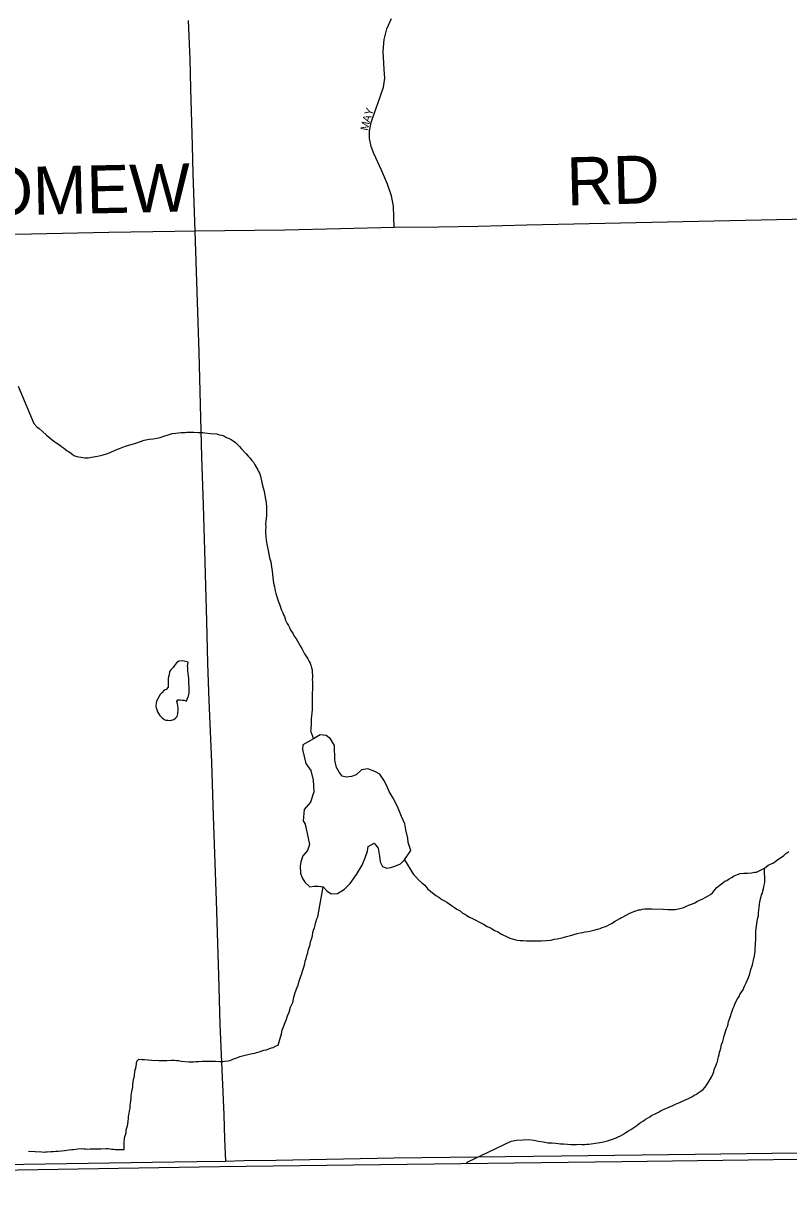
# Model space of a CAD drawing. Extents: x -10.1 to 68, y -9.5 to 29.2.
# Drawn here: x 3.456 to 4.36, y 16.795 to 18.175 of the extents above; entities that cross this region are included whole.
import ezdxf

# ---------------------------------------------------------------- set-up
doc = ezdxf.new("R2010")
doc.units = 0
for name, color, linetype in [('GM_X_Adjacent_County', 7, 'Continuous'), ('GM_X_County_Road', 7, 'Continuous'), ('GM_X_Minor_Lake', 7, 'Continuous'), ('GM_X_Minor_River', 7, 'Continuous'), ('GM_X_Township_Road', 7, 'Continuous'), ('GM_X_Township_Road_Text', 7, 'Continuous'), ('GM_X_Township_Subdivision', 7, 'Continuous'), ('GM_X_Township_Subdivision_Text', 7, 'Continuous')]:
    doc.layers.add(name, color=color, linetype=linetype)

msp = doc.modelspace()

# ---------------------------------------------------------------- linework, layer by layer
at = {"layer": 'GM_X_Adjacent_County'}
msp.add_lwpolyline([(8.9, 16.8967), (8.5023, 16.8904), (7.9665, 16.8821), (7.5233, 16.8774), (6.5083, 16.8667), (6.2435, 16.8638), (4.8206, 16.8372), (4.1632, 16.8285), (3.6875, 16.8223), (2.8045, 16.808), (2.1, 16.7954)], dxfattribs=at)
at = {"layer": 'GM_X_County_Road'}
msp.add_lwpolyline([(3.6506, 18.1785), (3.6523, 18.1327), (3.6533, 18.0978), (3.6553, 18.0303), (3.656, 17.9971), (3.6584, 17.9291), (3.6632, 17.7858), (3.6664, 17.6621), (3.6683, 17.6049), (3.6698, 17.5516), (3.6722, 17.4679), (3.6734, 17.4177), (3.6751, 17.374), (3.6782, 17.3012), (3.6802, 17.2377), (3.6838, 17.1371), (3.6864, 17.049), (3.6881, 16.9909), (3.6925, 16.8838), (3.6934, 16.8551), (3.6947, 16.8292)], dxfattribs=at)
at = {"layer": 'GM_X_Minor_Lake'}
for points in [[(3.6174, 17.3813), (3.613, 17.3731), (3.6126, 17.3708), (3.6123, 17.3678), (3.6128, 17.3655), (3.6136, 17.3633), (3.6144, 17.3606), (3.6156, 17.3587), (3.6172, 17.3561), (3.6195, 17.3539), (3.6222, 17.3517), (3.6241, 17.3509), (3.6264, 17.3506), (3.6283, 17.3503), (3.631, 17.3507), (3.6336, 17.3515), (3.6355, 17.3531), (3.6374, 17.355), (3.6384, 17.3581), (3.6384, 17.36), (3.6387, 17.3623), (3.6387, 17.3642), (3.6382, 17.368), (3.6378, 17.3699), (3.6373, 17.3729), (3.6384, 17.3749), (3.6415, 17.3749), (3.6434, 17.3746), (3.6457, 17.3743), (3.6484, 17.3732), (3.6495, 17.3755), (3.6502, 17.3774), (3.6509, 17.3793), (3.6512, 17.3812), (3.6516, 17.3835), (3.6519, 17.3858), (3.6518, 17.3904), (3.6513, 17.3942), (3.6512, 17.3968), (3.6512, 17.3991), (3.6512, 17.401), (3.6511, 17.4029), (3.6506, 17.4063), (3.6502, 17.409), (3.6502, 17.4113), (3.6501, 17.4132), (3.6497, 17.4143), (3.6507, 17.4193)], [(3.6507, 17.4193), (3.6442, 17.421), (3.6393, 17.4205), (3.6367, 17.4186), (3.6345, 17.4155), (3.6326, 17.4132), (3.63, 17.4104), (3.6285, 17.4085), (3.6279, 17.4043), (3.6272, 17.402), (3.6268, 17.4001), (3.6269, 17.3948), (3.627, 17.3925), (3.6267, 17.3898), (3.6245, 17.3871), (3.6222, 17.3863), (3.6192, 17.3832), (3.6174, 17.3813)], [(3.9063, 17.1855), (3.9137, 17.1966), (3.9106, 17.2061), (3.9101, 17.2114), (3.9077, 17.2212), (3.9065, 17.228), (3.9026, 17.2367), (3.898, 17.2488), (3.8929, 17.2586), (3.8883, 17.2666), (3.8855, 17.273), (3.8817, 17.2798), (3.877, 17.287), (3.8713, 17.2899), (3.863, 17.2932), (3.8554, 17.292), (3.849, 17.2862), (3.8437, 17.2842), (3.8373, 17.2834), (3.8324, 17.2845), (3.8289, 17.2894), (3.8258, 17.2947), (3.8238, 17.3034), (3.8236, 17.3209), (3.8186, 17.3288), (3.8136, 17.3325), (3.8064, 17.3336), (3.7985, 17.3285), (3.7861, 17.3215)], [(3.7861, 17.3215), (3.7858, 17.3162), (3.7898, 17.2995), (3.7955, 17.2912), (3.7983, 17.2799), (3.7992, 17.2662), (3.7952, 17.2536), (3.7878, 17.2451), (3.7864, 17.2318), (3.7888, 17.2277)], [(3.7888, 17.2277), (3.7939, 17.2038), (3.7917, 17.1966), (3.7861, 17.1904), (3.7836, 17.1832), (3.7829, 17.1782), (3.7833, 17.1698), (3.7853, 17.1642), (3.7884, 17.1593), (3.7945, 17.1536), (3.7994, 17.1545), (3.8047, 17.1545), (3.81, 17.1538), (3.8146, 17.149), (3.8196, 17.1452), (3.8272, 17.1457), (3.8355, 17.1507), (3.8422, 17.1577), (3.8496, 17.1684), (3.8563, 17.1791), (3.86, 17.1891), (3.8626, 17.1959), (3.8633, 17.2013), (3.8704, 17.2052), (3.875, 17.1995), (3.8767, 17.19), (3.8775, 17.1832), (3.8802, 17.1775), (3.8852, 17.1757), (3.8901, 17.1765), (3.895, 17.1781), (3.9014, 17.1808), (3.9063, 17.1855)]]:
    msp.add_lwpolyline(points, dxfattribs=at)
at = {"layer": 'GM_X_Minor_River'}
for points in [[(3.4494, 17.746), (3.4681, 17.7016), (3.4716, 17.6979), (3.4743, 17.6957), (3.4778, 17.6927), (3.4829, 17.6879), (3.4875, 17.6842), (3.4918, 17.6809), (3.4953, 17.6783), (3.4984, 17.6765), (3.5007, 17.6746), (3.503, 17.6728), (3.5053, 17.6713), (3.5076, 17.6694), (3.51, 17.668), (3.5127, 17.6661), (3.5154, 17.6639), (3.5188, 17.6628), (3.5284, 17.6612), (3.5322, 17.6612), (3.5364, 17.6617), (3.5409, 17.6626), (3.5455, 17.6635), (3.55, 17.6647), (3.5541, 17.6659), (3.5583, 17.6675), (3.5643, 17.67), (3.5692, 17.672), (3.5753, 17.6744), (3.5817, 17.6765), (3.5874, 17.6781), (3.593, 17.6801), (3.5987, 17.6818), (3.6044, 17.6831), (3.6093, 17.6835), (3.6135, 17.6844), (3.6176, 17.6853), (3.6218, 17.6865), (3.6267, 17.6881), (3.6316, 17.6898), (3.6358, 17.6902), (3.6392, 17.6907), (3.6422, 17.6911), (3.6449, 17.6912), (3.6468, 17.6912), (3.6487, 17.6913), (3.6514, 17.6914), (3.654, 17.6914), (3.6574, 17.6915), (3.6624, 17.6912), (3.6677, 17.691), (3.6704, 17.6906), (3.6769, 17.69), (3.6845, 17.6894), (3.6872, 17.6884), (3.6902, 17.6877), (3.6933, 17.6866), (3.696, 17.6851), (3.6991, 17.6841), (3.7014, 17.6826), (3.7037, 17.6811), (3.7064, 17.6793), (3.7088, 17.6767), (3.7111, 17.6744), (3.7131, 17.6722), (3.7189, 17.6659), (3.7216, 17.6629), (3.724, 17.6607), (3.7255, 17.6584), (3.7279, 17.6558), (3.7295, 17.6528), (3.7307, 17.6509), (3.7318, 17.649), (3.7327, 17.6468), (3.7338, 17.6449), (3.735, 17.643), (3.7355, 17.6408), (3.7363, 17.6373), (3.7371, 17.6339), (3.738, 17.6298), (3.7392, 17.6256), (3.7405, 17.6215), (3.7413, 17.6165), (3.7418, 17.612), (3.7427, 17.6082), (3.7432, 17.6025), (3.7433, 17.5979), (3.743, 17.593), (3.7427, 17.5892), (3.7424, 17.5857), (3.7421, 17.5827), (3.7422, 17.5793), (3.7419, 17.5755), (3.742, 17.572), (3.7425, 17.5679), (3.7429, 17.5633)], [(3.7429, 17.5633), (3.7439, 17.5569), (3.7451, 17.5516), (3.746, 17.547), (3.7468, 17.5428), (3.7481, 17.5379), (3.749, 17.5322), (3.7499, 17.5269), (3.7508, 17.5197), (3.7513, 17.5129), (3.7526, 17.5083), (3.753, 17.5061), (3.7534, 17.5038), (3.7543, 17.5004), (3.7572, 17.4909), (3.7584, 17.4879), (3.7596, 17.4845), (3.7608, 17.4808), (3.7624, 17.4777), (3.7632, 17.4755), (3.7644, 17.4732), (3.7656, 17.4691), (3.7676, 17.4653), (3.7692, 17.4627), (3.7704, 17.4604), (3.7716, 17.4574), (3.7732, 17.4552), (3.7748, 17.4529), (3.776, 17.4503), (3.7783, 17.4469), (3.7795, 17.445), (3.7811, 17.4424), (3.7831, 17.4386), (3.7847, 17.4356), (3.7863, 17.4322), (3.7882, 17.4292), (3.7898, 17.427), (3.7918, 17.4232), (3.7934, 17.4202), (3.7946, 17.418), (3.7954, 17.4157), (3.7962, 17.4127), (3.797, 17.4104), (3.7971, 17.407), (3.7976, 17.4036), (3.7976, 17.4009), (3.7973, 17.399), (3.7974, 17.3956), (3.7975, 17.3922), (3.7976, 17.388), (3.7973, 17.3823), (3.797, 17.3777), (3.7971, 17.3739), (3.7972, 17.3712), (3.7972, 17.3686), (3.7973, 17.3659), (3.797, 17.3629), (3.7967, 17.3594), (3.7964, 17.3556), (3.7961, 17.3526), (3.7959, 17.3453), (3.7956, 17.3419), (3.7956, 17.3392), (3.7953, 17.3381), (3.7985, 17.3285)], [(4.2681, 17.1445), (4.2707, 17.1468), (4.2729, 17.1496), (4.2755, 17.153), (4.2793, 17.1562), (4.2826, 17.1585), (4.2849, 17.1605), (4.2871, 17.1613), (4.2901, 17.1633), (4.2928, 17.1648), (4.2961, 17.1668), (4.2999, 17.1684), (4.3029, 17.1693), (4.3075, 17.1697), (4.312, 17.1698), (4.3166, 17.1703), (4.3204, 17.1708), (4.3223, 17.1708), (4.3272, 17.1732), (4.3317, 17.1756), (4.3362, 17.1792), (4.3418, 17.1816), (4.3441, 17.1831), (4.346, 17.1847), (4.3546, 17.1906), (4.3572, 17.1929), (4.3605, 17.1953)], [(3.9063, 17.1855), (3.9167, 17.1681), (3.9195, 17.1655), (3.923, 17.1621), (3.9265, 17.1588), (3.9304, 17.1555), (3.9339, 17.151), (3.9389, 17.1469), (3.9432, 17.1432), (3.9467, 17.1414), (3.949, 17.1399), (3.9513, 17.1384), (3.9536, 17.137), (3.9563, 17.1355), (3.959, 17.1337), (3.9617, 17.1314), (3.9652, 17.1292), (3.9683, 17.1274), (3.9721, 17.1252), (3.9745, 17.123), (3.9776, 17.1215), (3.9799, 17.1197), (3.983, 17.1178), (3.9868, 17.116), (3.9907, 17.1142), (3.9949, 17.1117), (3.9995, 17.1095), (4.0041, 17.1069), (4.0088, 17.1047), (4.0126, 17.1018), (4.0168, 17.1004), (4.0188, 17.0989), (4.0211, 17.0978), (4.0234, 17.0963), (4.0261, 17.0952), (4.0284, 17.0941), (4.0307, 17.0931), (4.0334, 17.092), (4.0361, 17.0913), (4.038, 17.0909), (4.0399, 17.0906), (4.0429, 17.0903), (4.0464, 17.09), (4.0506, 17.0897), (4.0681, 17.0897), (4.0738, 17.0902), (4.0791, 17.0907), (4.0836, 17.0916), (4.0867, 17.0921), (4.0886, 17.0925), (4.0905, 17.0929), (4.0939, 17.0937), (4.0976, 17.095), (4.1026, 17.0962), (4.1063, 17.0971), (4.1105, 17.0983), (4.1139, 17.0991), (4.1169, 17.0996), (4.12, 17.1004), (4.1234, 17.1009), (4.1268, 17.1017), (4.1302, 17.1022), (4.1344, 17.1034), (4.1374, 17.1042), (4.14, 17.1054), (4.1427, 17.1063), (4.1457, 17.1075), (4.1487, 17.1091), (4.1517, 17.1107), (4.1547, 17.1126), (4.1581, 17.1146), (4.1607, 17.1162), (4.1629, 17.1174), (4.1648, 17.1182), (4.172, 17.1221), (4.1772, 17.1245), (4.181, 17.1258), (4.1833, 17.1266), (4.1852, 17.1266), (4.1871, 17.1271), (4.1901, 17.1275), (4.1939, 17.1276), (4.1985, 17.1277), (4.2122, 17.1272), (4.2175, 17.127), (4.2206, 17.1267), (4.2236, 17.1267), (4.2263, 17.1268), (4.2301, 17.1277), (4.2335, 17.1285), (4.2365, 17.1293), (4.2395, 17.1309), (4.2433, 17.1325), (4.2467, 17.1337), (4.2493, 17.1349), (4.2527, 17.1365), (4.2561, 17.1381), (4.2591, 17.1393), (4.2617, 17.1409), (4.2651, 17.1429), (4.2681, 17.1445)], [(4.2959, 17.0123), (4.2969, 17.015), (4.2984, 17.0185), (4.2998, 17.0212), (4.3017, 17.0239), (4.3028, 17.0262), (4.305, 17.0297), (4.3065, 17.032), (4.3075, 17.0343), (4.3086, 17.037), (4.3101, 17.0401), (4.3119, 17.0435), (4.313, 17.0466), (4.3144, 17.0508), (4.3158, 17.0558), (4.3176, 17.0612), (4.319, 17.0669), (4.32, 17.0722), (4.3206, 17.0772), (4.3212, 17.0875), (4.3215, 17.0909), (4.3214, 17.0951), (4.3216, 17.1012), (4.3222, 17.1073), (4.3232, 17.113), (4.3239, 17.1168), (4.3246, 17.1199), (4.3249, 17.1226), (4.3252, 17.1264), (4.3255, 17.1294), (4.3258, 17.1325), (4.3265, 17.1363), (4.3276, 17.1405), (4.3282, 17.144), (4.3293, 17.1463), (4.33, 17.149), (4.3307, 17.1513), (4.3311, 17.1539), (4.3317, 17.157), (4.3321, 17.1589), (4.3317, 17.1756)], [(3.7082, 16.9514), (3.7116, 16.953), (3.7162, 16.9543), (3.7196, 16.9551), (3.7226, 16.9559), (3.7264, 16.9564), (3.7294, 16.9568), (3.7313, 16.9576), (3.7343, 16.9585), (3.737, 16.9593), (3.74, 16.9605), (3.7427, 16.9609), (3.7449, 16.9618), (3.7468, 16.9626), (3.7491, 16.9634), (3.751, 16.9638), (3.7547, 16.9654), (3.757, 16.9662), (3.7587, 16.9731), (3.7609, 16.9796), (3.7615, 16.9842), (3.7666, 16.9973), (3.768, 17.0011), (3.7698, 17.0053), (3.7716, 17.0114), (3.7741, 17.0168), (3.7755, 17.023), (3.7772, 17.0287), (3.779, 17.0337), (3.7805, 17.0375), (3.7815, 17.041), (3.7826, 17.0444), (3.7837, 17.0479), (3.7847, 17.0513), (3.7858, 17.054), (3.7869, 17.0575), (3.7883, 17.0624), (3.789, 17.0659), (3.79, 17.0689), (3.7907, 17.0724), (3.7918, 17.0755), (3.7925, 17.0789), (3.7935, 17.082), (3.7946, 17.0854), (3.7953, 17.0885), (3.7963, 17.0919), (3.7974, 17.0957), (3.7977, 17.0996), (3.7988, 17.1022), (3.7998, 17.1053), (3.8005, 17.1084), (3.8016, 17.1118), (3.8027, 17.1157), (3.8037, 17.1183), (3.8051, 17.1248), (3.81, 17.1538)], [(3.9796, 16.8275), (4.0324, 16.853), (4.0392, 16.8539), (4.0464, 16.8545), (4.0533, 16.8546), (4.059, 16.854), (4.0647, 16.853), (4.0705, 16.852), (4.0758, 16.8509), (4.0808, 16.8507), (4.085, 16.8504), (4.088, 16.8501), (4.0907, 16.8498), (4.0941, 16.8495), (4.0991, 16.8492), (4.1029, 16.8489), (4.1063, 16.849), (4.1097, 16.849), (4.1132, 16.8491), (4.1158, 16.8488), (4.1177, 16.8488), (4.1196, 16.8489), (4.1215, 16.8493), (4.1242, 16.8494), (4.1268, 16.8498), (4.1371, 16.8512), (4.1401, 16.8516), (4.1431, 16.8525), (4.1462, 16.8533), (4.1499, 16.8545), (4.1533, 16.8557), (4.1564, 16.8566), (4.159, 16.8578), (4.1616, 16.859), (4.1643, 16.8609), (4.168, 16.8629), (4.171, 16.8649), (4.174, 16.8665), (4.1763, 16.8681), (4.1785, 16.8696), (4.1811, 16.8712), (4.1838, 16.8736), (4.186, 16.8751), (4.1886, 16.8767), (4.1909, 16.8783), (4.1935, 16.8799), (4.1961, 16.8815), (4.1984, 16.883), (4.2033, 16.8854), (4.2074, 16.8874), (4.2097, 16.889), (4.2134, 16.8906), (4.2206, 16.8938), (4.2236, 16.895), (4.2266, 16.8966), (4.2307, 16.8982), (4.2334, 16.8994), (4.2364, 16.901), (4.2394, 16.9022), (4.242, 16.9034), (4.2443, 16.9046), (4.2466, 16.9058), (4.2488, 16.9074), (4.2514, 16.9086), (4.2533, 16.9098), (4.2571, 16.9125), (4.2589, 16.9137), (4.2615, 16.9168), (4.2634, 16.9191), (4.2648, 16.9214), (4.2696, 16.9295), (4.2707, 16.9319), (4.2718, 16.9349), (4.2725, 16.938), (4.2739, 16.9407), (4.275, 16.9441), (4.2761, 16.9468), (4.2768, 16.9495), (4.2774, 16.9526), (4.2781, 16.9552), (4.2788, 16.9579), (4.2796, 16.9602), (4.2803, 16.9629), (4.2809, 16.9671), (4.2824, 16.9706), (4.2834, 16.974), (4.2841, 16.9774), (4.2855, 16.9809), (4.2863, 16.9836), (4.287, 16.9859), (4.288, 16.9886), (4.2887, 16.9912), (4.2894, 16.9943), (4.2905, 16.997), (4.2912, 16.9993), (4.2919, 17.0016), (4.2923, 17.0035), (4.2934, 17.0054), (4.2941, 17.0077), (4.2948, 17.01), (4.2959, 17.0123)], [(3.4619, 16.8408), (3.4775, 16.8404), (3.4795, 16.84), (3.4817, 16.8401), (3.484, 16.8402), (3.4882, 16.8406), (3.4912, 16.8407), (3.4939, 16.8408), (3.4969, 16.8408), (3.5007, 16.8413), (3.5045, 16.8418), (3.5098, 16.8426), (3.5132, 16.8431), (3.5151, 16.8431), (3.5201, 16.8436), (3.5243, 16.8441), (3.5273, 16.8438), (3.5292, 16.8438), (3.5315, 16.8435), (3.5345, 16.8436), (3.5372, 16.8436), (3.5395, 16.8437), (3.5429, 16.8438), (3.5448, 16.8438), (3.5471, 16.8439), (3.5536, 16.844), (3.5558, 16.8441), (3.56, 16.8434), (3.5623, 16.8435), (3.5646, 16.8431), (3.568, 16.8428), (3.5703, 16.8429), (3.5722, 16.8429), (3.5749, 16.843), (3.5748, 16.8468), (3.5747, 16.8498), (3.5747, 16.8517), (3.5754, 16.8555), (3.5757, 16.8582), (3.5764, 16.8605), (3.5771, 16.8632), (3.5774, 16.8662), (3.5781, 16.8685), (3.5788, 16.8708), (3.5791, 16.8731), (3.5794, 16.8766), (3.5798, 16.8796), (3.5801, 16.8819), (3.5804, 16.8838), (3.5808, 16.8857), (3.5811, 16.8888), (3.5818, 16.8918), (3.5821, 16.8953), (3.5824, 16.8979), (3.5827, 16.9006), (3.583, 16.9033), (3.5833, 16.9063), (3.5836, 16.9094), (3.584, 16.9113), (3.585, 16.917), (3.5853, 16.9201), (3.5856, 16.9231), (3.5859, 16.9258), (3.5866, 16.9281), (3.587, 16.93), (3.5876, 16.9357), (3.589, 16.9411), (3.5893, 16.9445), (3.59, 16.9476), (3.5922, 16.9499), (3.596, 16.9496), (3.5991, 16.9493), (3.6033, 16.949), (3.6075, 16.9487), (3.6105, 16.9484), (3.6132, 16.9485), (3.6159, 16.9482), (3.6185, 16.9482), (3.6216, 16.9483), (3.6254, 16.9484), (3.6307, 16.9485), (3.6341, 16.9486), (3.6368, 16.9483), (3.6391, 16.9483), (3.6421, 16.9476), (3.6513, 16.9467), (3.6539, 16.9468), (3.657, 16.9468), (3.6596, 16.9469), (3.6631, 16.947), (3.6672, 16.9474), (3.6726, 16.9476), (3.6779, 16.9473), (3.6828, 16.9474), (3.6878, 16.9471), (3.6916, 16.9472), (3.6939, 16.9473), (3.6977, 16.9477), (3.7003, 16.9482), (3.7033, 16.9498), (3.7082, 16.9514)]]:
    msp.add_lwpolyline(points, dxfattribs=at)
at = {"layer": 'GM_X_Township_Road'}
for points in [[(4.7732, 17.9507), (4.6614, 17.9487), (4.5354, 17.9464), (4.4015, 17.9439), (4.0507, 17.9362), (3.9932, 17.9347), (3.9463, 17.934), (3.8941, 17.9335), (3.8306, 17.932), (3.7646, 17.9303), (3.6584, 17.9291)], [(3.6584, 17.9291), (3.6348, 17.9286), (3.5569, 17.9274), (3.4652, 17.9257), (3.3805, 17.9243), (3.3033, 17.9214), (3.2228, 17.9197), (3.1564, 17.919), (3.134, 17.9187), (3.0925, 17.918), (3.0317, 17.9163), (2.8981, 17.9134), (2.8896, 17.9136), (2.8636, 17.9129), (2.8106, 17.9106), (2.7471, 17.9096), (2.6306, 17.9068), (2.5068, 17.9039), (2.3976, 17.9012), (2.3752, 17.9006), (2.3549, 17.9003), (2.2472, 17.8974), (2.1683, 17.895), (2.1, 17.8931)], [(3.6947, 16.8292), (3.7163, 16.8298), (3.7546, 16.8305), (3.8936, 16.8331), (4.092, 16.8355), (4.2497, 16.8375), (4.371, 16.8391), (4.4448, 16.8401), (4.5032, 16.8407), (4.6144, 16.8428), (4.7173, 16.8441), (4.7504, 16.8446), (4.7994, 16.8454), (4.8224, 16.8458)], [(3.2258, 16.8223), (3.3087, 16.8235), (3.3549, 16.8239), (3.6078, 16.8278), (3.6606, 16.8286), (3.6947, 16.8292)]]:
    msp.add_lwpolyline(points, dxfattribs=at)
at = {"layer": 'GM_X_Township_Subdivision'}
msp.add_lwpolyline([(3.8941, 17.9335), (3.8931, 17.9589), (3.8908, 17.9708), (3.8861, 17.9848), (3.8789, 18.0012), (3.8699, 18.0209), (3.8667, 18.0293), (3.8649, 18.0388), (3.8649, 18.0475), (3.8667, 18.0577), (3.8707, 18.0692), (3.8774, 18.0881), (3.8814, 18.0993), (3.8831, 18.1102), (3.8824, 18.1205), (3.8809, 18.1419), (3.8821, 18.1558), (3.8853, 18.1683), (3.8908, 18.1807)], dxfattribs=at)

# ---------------------------------------------------------------- texts
at = {"layer": 'GM_X_Township_Road_Text'}
for s, height, rotation, p in [('RD', 0.05682, 1.4806, (4.0986, 17.9596)), ('BARTHOLOMEW', 0.056818, 1.2171, (3.0498, 17.9397))]:
    msp.add_text(s, height=height, rotation=rotation, dxfattribs=at).set_placement(p)
at = {"layer": 'GM_X_Township_Subdivision_Text'}
for s, rotation, p in [('Y', 70.7564, (3.8675, 18.065)), ('M', 79.3188, (3.8633, 18.0475)), ('A', 72.7125, (3.8651, 18.0571))]:
    msp.add_text(s, height=0.00947, rotation=rotation, dxfattribs=at).set_placement(p)

doc.saveas('drawing.dxf')
